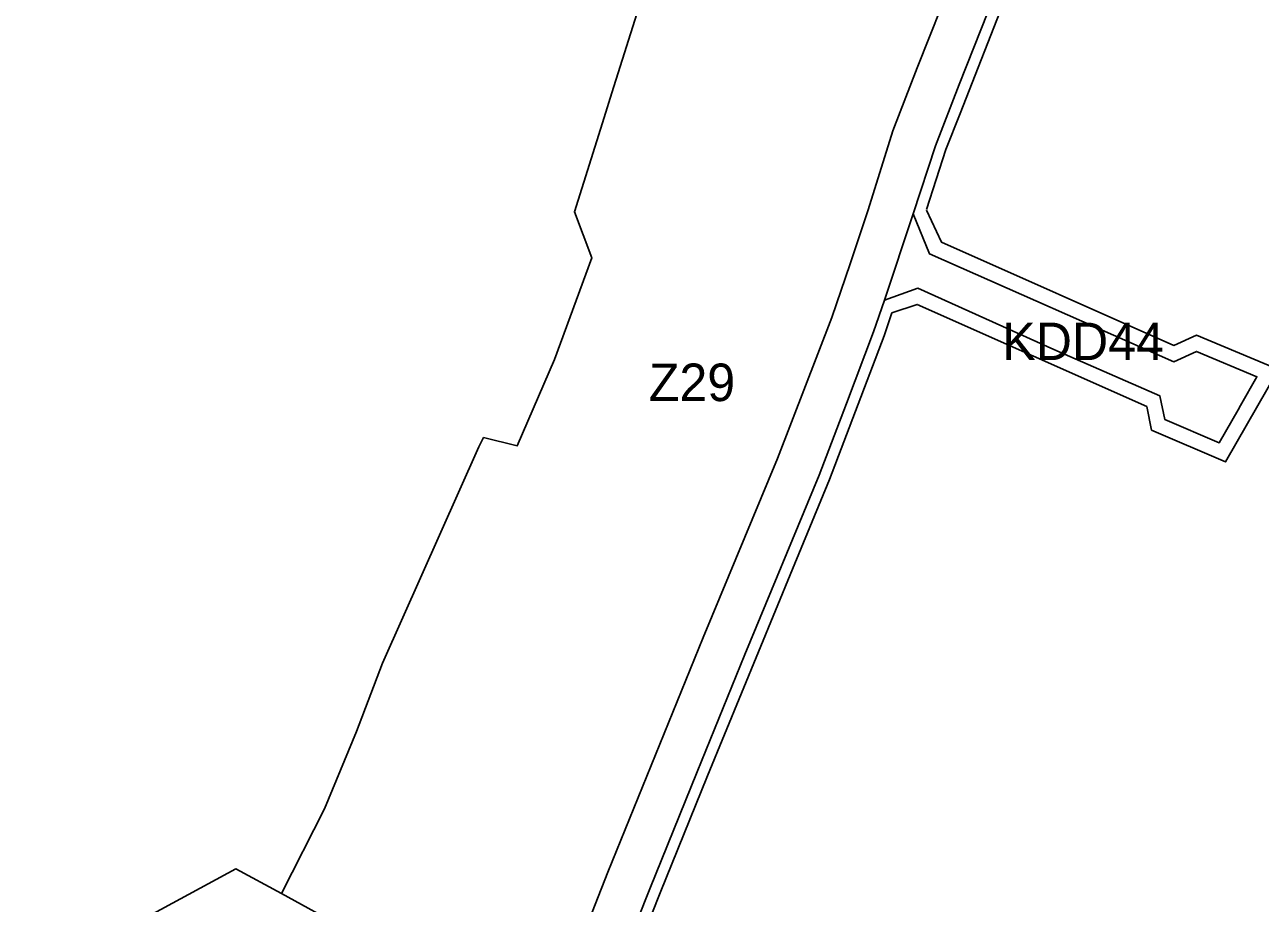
# Model space of a CAD drawing. Extents: x 7428841 to 7433518, y 5545054 to 5546840.
# Drawn here: x 7432132.2 to 7432461.8, y 5545850.4 to 5546084.6 of the extents above; entities that cross this region are included whole.
import ezdxf

# ---------------------------------------------------------------- set-up
doc = ezdxf.new("R2010")
doc.units = 0
for name, color, linetype in [('linie_rozgraniczajace', 7, 'Continuous'), ('linie_zabudowy_nieprzekraczalne', 7, 'Continuous'), ('oznaczenia_przeznaczen', 7, 'Continuous')]:
    doc.layers.add(name, color=color, linetype=linetype)

msp = doc.modelspace()

# ---------------------------------------------------------------- linework, layer by layer
at = {"layer": 'linie_rozgraniczajace'}
for points in [[(7432132.18, 5545621.69), (7432147.9, 5545639.12), (7432154.88, 5545648.03), (7432210.86, 5545705.54), (7432222.9, 5545721.64), (7432232.08, 5545736.14), (7432244.76, 5545759.7), (7432253.45, 5545777.62), (7432262.14, 5545795.55), (7432271.44, 5545817.17), (7432287.75, 5545858.73), (7432313.15, 5545921.27), (7432332.96, 5545968.95), (7432347.45, 5546006.55), (7432352.33, 5546020.89), (7432357.2, 5546035.24), (7432363.75, 5546056.3), (7432370.28, 5546073.1), (7432379.89, 5546097.52)], [(7432379.89, 5546097.52), (7432370.28, 5546073.1), (7432363.75, 5546056.3), (7432357.2, 5546035.24), (7432352.33, 5546020.89), (7432347.45, 5546006.55), (7432332.96, 5545968.95), (7432313.15, 5545921.27), (7432287.75, 5545858.73), (7432271.44, 5545817.17)], [(7432391.09, 5546093.19), (7432381.44, 5546068.71), (7432375.09, 5546052.35), (7432369.21, 5546034.21), (7432361.5, 5546011.22), (7432358.63, 5546002.71), (7432351.37, 5545983.6), (7432344.11, 5545964.49), (7432324.25, 5545916.71), (7432311.57, 5545885.49), (7432298.89, 5545854.26), (7432292.35, 5545837.77)], [(7432292.35, 5545837.77), (7432298.89, 5545854.26), (7432311.57, 5545885.49), (7432324.25, 5545916.71), (7432344.11, 5545964.49), (7432351.37, 5545983.6), (7432358.63, 5546002.71), (7432361.5, 5546011.22), (7432370.43, 5546014.36), (7432406.65, 5545998.02), (7432434.98, 5545985.67), (7432436.27, 5545979.4), (7432450.79, 5545973.13), (7432455.83, 5545981.94), (7432456.47, 5545983.06), (7432460.87, 5545990.76), (7432444.79, 5545997.53), (7432438.71, 5545994.74), (7432373.53, 5546023.5), (7432369.21, 5546034.21), (7432375.09, 5546052.35), (7432381.44, 5546068.71), (7432391.09, 5546093.19)], [(7432296.62, 5546091.15), (7432288.79, 5546066.47), (7432286.79, 5546059.9), (7432278.81, 5546034.7), (7432283.49, 5546022.5), (7432273.46, 5545995.35), (7432263.57, 5545972.37), (7432254.57, 5545974.57), (7432253.33, 5545972.05), (7432227.66, 5545914.38), (7432220.68, 5545896.17), (7432212.13, 5545875.6), (7432200.67, 5545852.98), (7432188.47, 5545859.56), (7432146.36, 5545836.73)], [(7432217.5, 5545843.79), (7432200.67, 5545852.98), (7432212.13, 5545875.6), (7432220.68, 5545896.17), (7432227.66, 5545914.38), (7432253.33, 5545972.05), (7432254.57, 5545974.57), (7432263.57, 5545972.37), (7432273.46, 5545995.35), (7432283.49, 5546022.5), (7432278.81, 5546034.7), (7432286.79, 5546059.9), (7432288.79, 5546066.47), (7432296.62, 5546091.15)], [(7432146.36, 5545836.73), (7432188.47, 5545859.56), (7432200.67, 5545852.98), (7432217.5, 5545843.79)]]:
    msp.add_lwpolyline(points, dxfattribs=at)
msp.add_lwpolyline([(7432361.5, 5546011.22), (7432369.21, 5546034.21), (7432373.53, 5546023.5), (7432438.71, 5545994.74), (7432444.79, 5545997.53), (7432460.87, 5545990.76), (7432456.47, 5545983.06), (7432455.83, 5545981.94), (7432450.79, 5545973.13), (7432436.27, 5545979.4), (7432434.98, 5545985.67), (7432406.65, 5545998.02), (7432370.43, 5546014.36)], close=True, dxfattribs=at)
at = {"layer": 'linie_zabudowy_nieprzekraczalne'}
for points in [[(7432593.63, 5546074.54), (7432591.98, 5546073.8), (7432578.61, 5546074.63), (7432567.22, 5546076.58), (7432550.63, 5546082.14), (7432532.81, 5546089.84), (7432527.7, 5546092.2), (7432485.7, 5546109.81), (7432458.51, 5546126.69), (7432452.41, 5546132.85), (7432435.28, 5546145.13), (7432424.99, 5546147.09), (7432418.39, 5546143.95), (7432409.65, 5546135.03), (7432399.48, 5546106.93), (7432393.88, 5546092.12), (7432381.68, 5546060.94), (7432377.92, 5546051.34), (7432372.72, 5546035.31)], [(7432372.69, 5546035.2), (7432376.74, 5546026.61), (7432438.68, 5545999.12), (7432444.72, 5546001.89), (7432466.59, 5545992.69), (7432452.49, 5545968.04), (7432432.77, 5545976.56), (7432431.48, 5545982.83), (7432370.24, 5546010.05), (7432363.46, 5546007.84)], [(7432363.46, 5546007.84), (7432361.46, 5546001.7), (7432346.89, 5545963.38), (7432336.96, 5545939.48), (7432314.35, 5545884.36), (7432301.67, 5545853.15), (7432291.29, 5545827.01)]]:
    msp.add_lwpolyline(points, dxfattribs=at)

# ---------------------------------------------------------------- texts
at = {"layer": 'oznaczenia_przeznaczen'}
for s, p in [('KDD44', (7432392.95, 5545995.21)), ('Z29', (7432298.65, 5545984.28))]:
    msp.add_text(s, height=10, dxfattribs=at).set_placement(p)

doc.saveas('drawing.dxf')
